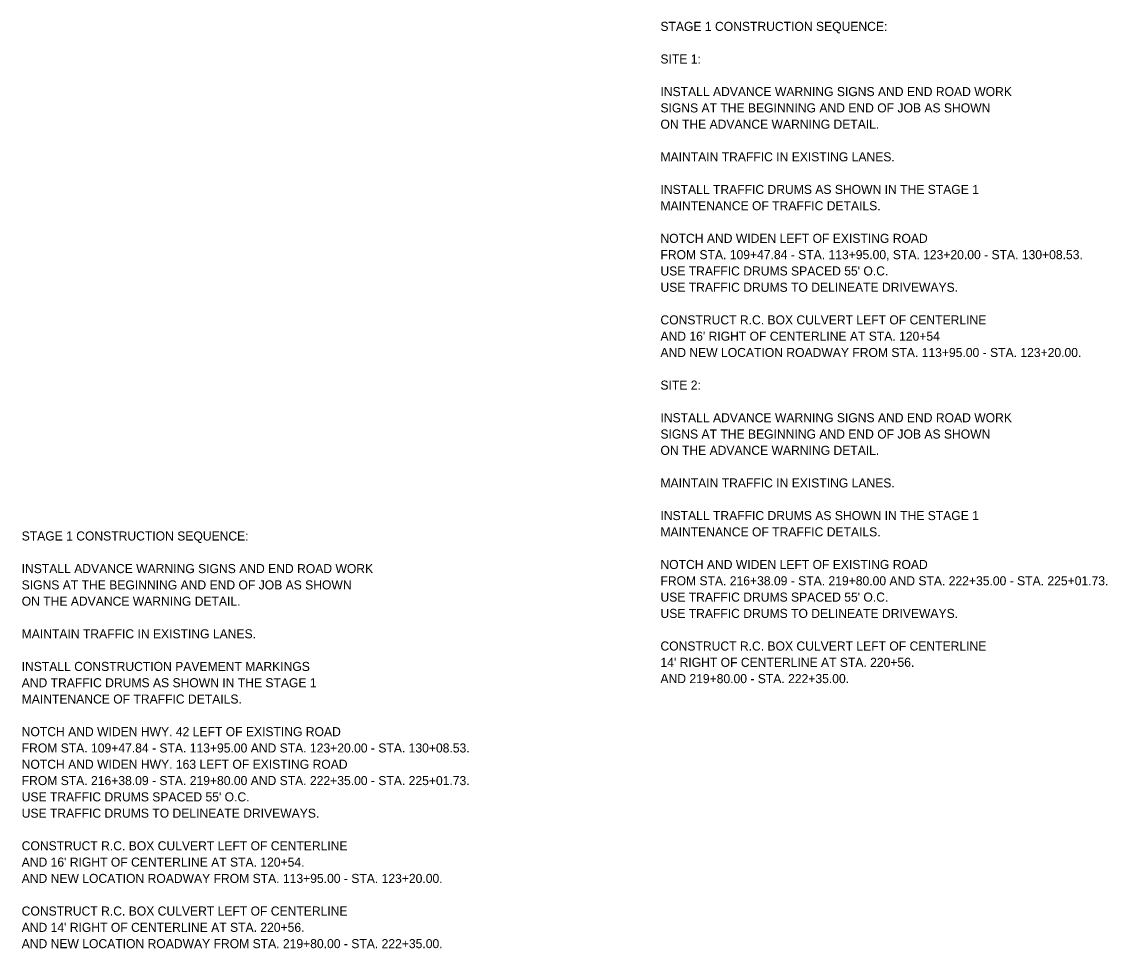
# Model space of a CAD drawing. Extents: x 1678017 to 1687792, y 404433 to 413488.
# Drawn here: x 1681435 to 1682154, y 411777 to 412390 of the extents above; entities that cross this region are included whole.
import ezdxf

# ---------------------------------------------------------------- set-up
doc = ezdxf.new("R2010")
doc.units = 0
doc.layers.add('S_MSC_PT_SYM', color=7, linetype='Continuous')

msp = doc.modelspace()

# ---------------------------------------------------------------- texts
at = {"layer": 'S_MSC_PT_SYM'}
for s, p in [('STAGE 1 CONSTRUCTION SEQUENCE:', (1681857.89, 412384.36)), ('SITE 1:', (1681857.89, 412362.76)), ('INSTALL ADVANCE WARNING SIGNS AND END ROAD WORK', (1681857.89, 412341.16)), ('SIGNS AT THE BEGINNING AND END OF JOB AS SHOWN', (1681857.89, 412330.36)), ('ON THE ADVANCE WARNING DETAIL.', (1681857.89, 412319.56)), ('MAINTAIN TRAFFIC IN EXISTING LANES.', (1681857.89, 412297.96)), ('INSTALL TRAFFIC DRUMS AS SHOWN IN THE STAGE 1', (1681857.89, 412276.36)), ('MAINTENANCE OF TRAFFIC DETAILS.', (1681857.89, 412265.56)), ('NOTCH AND WIDEN LEFT OF EXISTING ROAD ', (1681857.89, 412243.96)), ('FROM STA. 109+47.84 - STA. 113+95.00, STA. 123+20.00 - STA. 130+08.53.', (1681857.89, 412233.16)), ("USE TRAFFIC DRUMS SPACED 55' O.C.", (1681857.89, 412222.36)), ('USE TRAFFIC DRUMS TO DELINEATE DRIVEWAYS.', (1681857.89, 412211.56)), ('CONSTRUCT R.C. BOX CULVERT LEFT OF CENTERLINE', (1681857.89, 412189.96)), ("AND 16' RIGHT OF CENTERLINE AT STA. 120+54", (1681857.89, 412179.16)), ('AND NEW LOCATION ROADWAY FROM STA. 113+95.00 - STA. 123+20.00.', (1681857.89, 412168.36)), ('SITE 2:', (1681857.89, 412146.76)), ('INSTALL ADVANCE WARNING SIGNS AND END ROAD WORK', (1681857.89, 412125.16)), ('SIGNS AT THE BEGINNING AND END OF JOB AS SHOWN', (1681857.89, 412114.36)), ('ON THE ADVANCE WARNING DETAIL.', (1681857.89, 412103.56)), ('MAINTAIN TRAFFIC IN EXISTING LANES.', (1681857.89, 412081.96)), ('INSTALL TRAFFIC DRUMS AS SHOWN IN THE STAGE 1', (1681857.89, 412060.36)), ('STAGE 1 CONSTRUCTION SEQUENCE:', (1681434.97, 412046.84)), ('MAINTENANCE OF TRAFFIC DETAILS.', (1681857.89, 412049.56)), ('INSTALL ADVANCE WARNING SIGNS AND END ROAD WORK', (1681434.97, 412025.24)), ('NOTCH AND WIDEN LEFT OF EXISTING ROAD ', (1681857.89, 412027.96)), ('SIGNS AT THE BEGINNING AND END OF JOB AS SHOWN', (1681434.97, 412014.44)), ('FROM STA. 216+38.09 - STA. 219+80.00 AND STA. 222+35.00 - STA. 225+01.73.', (1681857.89, 412017.16)), ('ON THE ADVANCE WARNING DETAIL.', (1681434.97, 412003.64)), ("USE TRAFFIC DRUMS SPACED 55' O.C.", (1681857.89, 412006.36)), ('USE TRAFFIC DRUMS TO DELINEATE DRIVEWAYS.', (1681857.89, 411995.56)), ('MAINTAIN TRAFFIC IN EXISTING LANES.', (1681434.97, 411982.04)), ('CONSTRUCT R.C. BOX CULVERT LEFT OF CENTERLINE', (1681857.89, 411973.96)), ('INSTALL CONSTRUCTION PAVEMENT MARKINGS', (1681434.97, 411960.44)), ("14' RIGHT OF CENTERLINE AT STA. 220+56.", (1681857.89, 411963.16)), ('AND TRAFFIC DRUMS AS SHOWN IN THE STAGE 1', (1681434.97, 411949.64)), ('AND 219+80.00 - STA. 222+35.00.', (1681857.89, 411952.36)), ('MAINTENANCE OF TRAFFIC DETAILS.', (1681434.97, 411938.84)), ('NOTCH AND WIDEN HWY. 42 LEFT OF EXISTING ROAD ', (1681434.97, 411917.24)), ('FROM STA. 109+47.84 - STA. 113+95.00 AND STA. 123+20.00 - STA. 130+08.53.', (1681434.97, 411906.44)), ('NOTCH AND WIDEN HWY. 163 LEFT OF EXISTING ROAD', (1681434.97, 411895.64)), ('FROM STA. 216+38.09 - STA. 219+80.00 AND STA. 222+35.00 - STA. 225+01.73.', (1681434.97, 411884.84)), ("USE TRAFFIC DRUMS SPACED 55' O.C.", (1681434.97, 411874.04)), ('USE TRAFFIC DRUMS TO DELINEATE DRIVEWAYS.', (1681434.97, 411863.24)), ('CONSTRUCT R.C. BOX CULVERT LEFT OF CENTERLINE', (1681434.97, 411841.64)), ("AND 16' RIGHT OF CENTERLINE AT STA. 120+54.", (1681434.97, 411830.84)), ('AND NEW LOCATION ROADWAY FROM STA. 113+95.00 - STA. 123+20.00.', (1681434.97, 411820.04)), ('CONSTRUCT R.C. BOX CULVERT LEFT OF CENTERLINE', (1681434.97, 411798.44)), ("AND 14' RIGHT OF CENTERLINE AT STA. 220+56.", (1681434.97, 411787.64)), ('AND NEW LOCATION ROADWAY FROM STA. 219+80.00 - STA. 222+35.00.', (1681434.97, 411776.84))]:
    msp.add_text(s, height=6, dxfattribs=at).set_placement(p)

doc.saveas('drawing.dxf')
